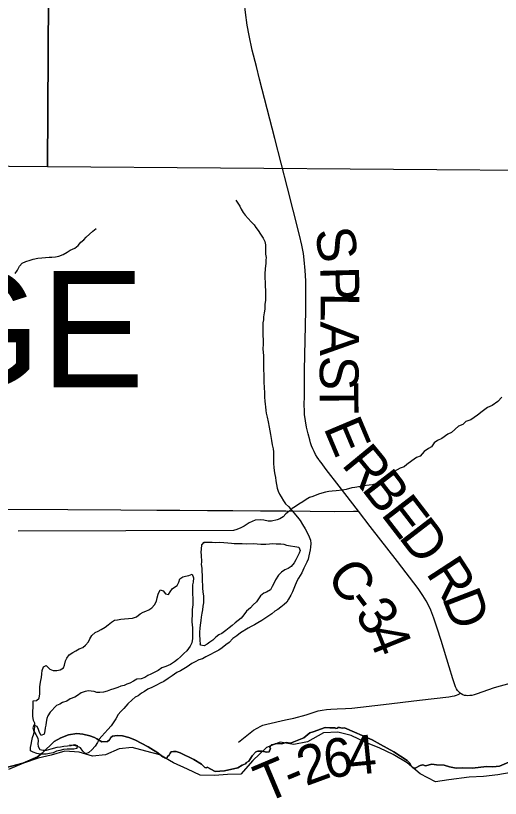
# Model space of a CAD drawing. Extents: x 0 to 34, y 0 to 22.
# Drawn here: x 4.767 to 5.123, y 17.478 to 18.052 of the extents above; entities that cross this region are included whole.
import ezdxf

# ---------------------------------------------------------------- set-up
doc = ezdxf.new("R2010")
doc.units = 0
for name, color, linetype in [('GM_X_Corporation', 7, 'Continuous'), ('GM_X_County_Road', 7, 'Continuous'), ('GM_X_County_Road_Text', 7, 'Continuous'), ('GM_X_Major_Lake', 7, 'Continuous'), ('GM_X_Minor_River', 7, 'Continuous'), ('GM_X_Township_Road', 7, 'Continuous'), ('GM_X_Township_Road_Text', 7, 'Continuous'), ('GM_X_Township_Text', 7, 'Continuous')]:
    doc.layers.add(name, color=color, linetype=linetype)

msp = doc.modelspace()

# ---------------------------------------------------------------- linework, layer by layer
at = {"layer": 'GM_X_Corporation'}
for points in [[(4.78631, 18.43953), (4.79371, 18.43949), (4.7909, 17.94084), (4.28639, 17.94519), (4.29299, 18.44647)], [(5.2907, 18.43288), (5.30482, 18.43261), (5.30041, 17.93698), (5.29864, 17.93686), (4.7909, 17.94084), (4.79371, 18.43949)]]:
    msp.add_lwpolyline(points, close=True, dxfattribs=at)
for points in [[(4.75985, 17.50015), (4.77274, 17.50363), (4.78345, 17.50836), (4.78698, 17.51101), (4.79573, 17.51947), (4.80055, 17.52212), (4.8063, 17.52438), (4.81225, 17.52546), (4.81677, 17.52502), (4.82183, 17.5236), (4.82532, 17.52247), (4.82704, 17.52153), (4.83073, 17.51927), (4.83496, 17.51957), (4.83628, 17.5207), (4.83727, 17.52247), (4.8385, 17.5234), (4.84022, 17.52375), (4.84228, 17.52394), (4.84597, 17.5236), (4.85044, 17.52242), (4.85486, 17.52075), (4.86465, 17.51563), (4.86863, 17.51328), (4.87113, 17.51165), (4.87546, 17.50821), (4.87728, 17.50738), (4.87861, 17.50758), (4.87885, 17.50856), (4.88008, 17.50944), (4.88082, 17.51092), (4.8817, 17.51205), (4.88337, 17.51229), (4.88519, 17.5122), (4.88824, 17.51111), (4.89817, 17.50644), (4.90382, 17.50286), (4.90632, 17.50054), (4.90752, 17.50019), (4.90795, 17.50064), (4.91399, 17.49765), (4.92063, 17.49804), (4.93056, 17.50015), (4.9338, 17.50207), (4.93616, 17.50305), (4.93695, 17.50418), (4.93851, 17.50511), (4.94108, 17.509), (4.94378, 17.512), (4.94506, 17.51249), (4.94811, 17.51244), (4.95179, 17.51175), (4.95346, 17.51195), (4.95435, 17.5147), (4.95386, 17.51519), (4.9544, 17.51642), (4.95528, 17.51711), (4.95617, 17.51721), (4.95794, 17.5178), (4.96015, 17.51804), (4.96275, 17.5179), (4.966, 17.51868), (4.96909, 17.51834), (4.97897, 17.52217), (4.98345, 17.52601), (4.9858, 17.52655), (4.9946, 17.52979), (4.99795, 17.52959), (5.00188, 17.52954), (5.00237, 17.52915), (5.00355, 17.5293), (5.0038, 17.52984), (5.00522, 17.52989), (5.00704, 17.5294), (5.00876, 17.52945), (5.02896, 17.5208), (5.03525, 17.51741), (5.04508, 17.51185), (5.05467, 17.50571), (5.05653, 17.50399), (5.05781, 17.50123), (5.05899, 17.50025), (5.06061, 17.5001), (5.0642, 17.50192), (5.06622, 17.50232), (5.06809, 17.50173), (5.07276, 17.503), (5.07615, 17.50232), (5.08195, 17.50212), (5.08578, 17.50099), (5.09074, 17.49991), (5.09571, 17.50025), (5.10244, 17.49991), (5.11311, 17.50109), (5.11753, 17.50084), (5.12255, 17.50153), (5.131, 17.50507)], [(5.131, 17.50507), (5.12255, 17.50153), (5.11753, 17.50084), (5.11311, 17.50109), (5.10244, 17.49991), (5.09571, 17.50025), (5.09074, 17.49991), (5.08578, 17.50099), (5.08195, 17.50212), (5.07615, 17.50232), (5.07276, 17.503), (5.06809, 17.50173), (5.06622, 17.50232), (5.0642, 17.50192), (5.06061, 17.5001), (5.05899, 17.50025), (5.05781, 17.50123), (5.05653, 17.50399), (5.05467, 17.50571), (5.04508, 17.51185), (5.03525, 17.51741), (5.02896, 17.5208), (5.00876, 17.52945), (5.00704, 17.5294), (5.00522, 17.52989), (5.0038, 17.52984), (5.00355, 17.5293), (5.00237, 17.52915), (5.00188, 17.52954), (4.99795, 17.52959), (4.9946, 17.52979), (4.9858, 17.52655), (4.98345, 17.52601), (4.97897, 17.52217), (4.96909, 17.51834), (4.966, 17.51868), (4.96275, 17.5179), (4.96015, 17.51804), (4.95794, 17.5178), (4.95617, 17.51721), (4.95528, 17.51711), (4.9544, 17.51642), (4.95386, 17.51519), (4.95435, 17.5147), (4.95346, 17.51195), (4.95179, 17.51175), (4.94811, 17.51244), (4.94506, 17.51249), (4.94378, 17.512), (4.94108, 17.509), (4.93851, 17.50511), (4.93695, 17.50418), (4.93616, 17.50305), (4.9338, 17.50207), (4.93056, 17.50015), (4.92063, 17.49804), (4.91399, 17.49765), (4.90795, 17.50064), (4.90752, 17.50019), (4.90632, 17.50054), (4.90382, 17.50286), (4.89817, 17.50644), (4.88824, 17.51111), (4.88519, 17.5122), (4.88337, 17.51229), (4.8817, 17.51205), (4.88082, 17.51092), (4.88008, 17.50944), (4.87885, 17.50856), (4.87861, 17.50758), (4.87728, 17.50738), (4.87546, 17.50821), (4.87113, 17.51165), (4.86863, 17.51328), (4.86465, 17.51563), (4.85486, 17.52075), (4.85044, 17.52242), (4.84597, 17.5236), (4.84228, 17.52394), (4.84022, 17.52375), (4.8385, 17.5234), (4.83727, 17.52247), (4.83628, 17.5207), (4.83496, 17.51957), (4.83073, 17.51927), (4.82704, 17.52153), (4.82532, 17.52247), (4.82183, 17.5236), (4.81677, 17.52502), (4.81225, 17.52546), (4.8063, 17.52438), (4.80055, 17.52212), (4.79573, 17.51947), (4.78698, 17.51101), (4.78345, 17.50836), (4.77274, 17.50363), (4.75985, 17.50015)]]:
    msp.add_lwpolyline(points, dxfattribs=at)
at = {"layer": 'GM_X_County_Road'}
for points in [[(4.94648, 18.00525), (4.94411, 18.01443), (4.94111, 18.02652), (4.93882, 18.03718), (4.93744, 18.04485), (4.93608, 18.0541), (4.93546, 18.06031), (4.93524, 18.06499), (4.93522, 18.07434), (4.93569, 18.08834), (4.93636, 18.1018)], [(4.9902, 17.72584), (4.98994, 17.7262), (4.98872, 17.72797), (4.98753, 17.72992), (4.98648, 17.73208), (4.98551, 17.73418), (4.98461, 17.73634), (4.98386, 17.73851), (4.98322, 17.74083), (4.98199, 17.74501), (4.98087, 17.74995), (4.98013, 17.75458), (4.97953, 17.75921), (4.97938, 17.76258), (4.97923, 17.76579), (4.9793, 17.77326), (4.97952, 17.79187), (4.98033, 17.83546), (4.98051, 17.851), (4.9804, 17.8572), (4.97996, 17.86495), (4.97927, 17.87267), (4.97864, 17.87727), (4.97749, 17.88335), (4.9757, 17.8909), (4.97109, 17.90899), (4.96694, 17.92557), (4.95771, 17.96173), (4.94648, 18.00525)], [(5.01914, 17.68832), (5.0049, 17.70683), (4.99524, 17.71903), (4.99154, 17.72405), (4.9902, 17.72584)], [(4.5969, 17.69027), (4.60848, 17.69021), (4.62713, 17.69011), (4.63955, 17.68998), (4.65974, 17.69015), (4.67061, 17.68997), (4.69856, 17.69002), (4.75604, 17.68978), (4.80574, 17.68966), (4.84457, 17.68932), (4.87097, 17.68923), (4.88806, 17.68922), (4.90825, 17.68887), (4.92689, 17.68884), (4.94708, 17.68868), (4.96572, 17.68856), (5.00144, 17.68822), (5.01541, 17.6883), (5.01914, 17.68832)], [(5.09373, 17.55489), (5.09309, 17.55543), (5.09243, 17.55608), (5.09171, 17.55697), (5.09092, 17.55821), (5.09021, 17.55955), (5.08963, 17.561), (5.08826, 17.56547), (5.08553, 17.57438), (5.07961, 17.59371), (5.07685, 17.60261), (5.07431, 17.60994), (5.07205, 17.61572), (5.07016, 17.61994), (5.0687, 17.62266), (5.06627, 17.6266), (5.0627, 17.63166), (5.04768, 17.65149), (5.02765, 17.67726), (5.01914, 17.68832)], [(5.13646, 17.56373), (5.12295, 17.56022), (5.11852, 17.55885), (5.10531, 17.55416), (5.10379, 17.55371), (5.10223, 17.55338), (5.10077, 17.55317), (5.09932, 17.55312), (5.09814, 17.55319), (5.09685, 17.55338), (5.09557, 17.55381), (5.09439, 17.55443), (5.09373, 17.55489)]]:
    msp.add_lwpolyline(points, dxfattribs=at)
at = {"layer": 'GM_X_Major_Lake'}
for points in [[(5.13104, 17.4968), (5.12137, 17.49509), (5.11074, 17.49395), (5.10012, 17.49337), (5.08532, 17.49147), (5.07564, 17.48995), (5.06426, 17.49584), (5.05477, 17.50382), (5.04452, 17.5099), (5.03465, 17.51465), (5.02441, 17.51884), (5.01359, 17.52397), (5.00392, 17.52644), (4.99348, 17.52586), (4.98153, 17.5194), (4.97147, 17.51731), (4.9616, 17.51902)], [(4.9616, 17.51902), (4.95155, 17.51502), (4.94149, 17.50571), (4.93277, 17.49563), (4.9229, 17.49544), (4.91341, 17.49449), (4.90298, 17.49487), (4.89349, 17.49924), (4.88325, 17.50399), (4.87319, 17.50969), (4.86294, 17.51235), (4.85308, 17.5152), (4.8434, 17.51425), (4.83334, 17.50987), (4.82386, 17.50873), (4.81399, 17.51177), (4.80355, 17.51253), (4.7935, 17.50949), (4.78401, 17.5074), (4.7732, 17.50359), (4.76219, 17.49903)]]:
    msp.add_lwpolyline(points, dxfattribs=at)
at = {"layer": 'GM_X_Minor_River'}
for points in [[(4.92908, 17.91636), (4.93061, 17.91428), (4.93195, 17.912), (4.93291, 17.90992), (4.93444, 17.90745), (4.93578, 17.90537), (4.93807, 17.90291), (4.94036, 17.90064), (4.94246, 17.89837), (4.9438, 17.89628), (4.94533, 17.8942), (4.94724, 17.89155), (4.94897, 17.88852), (4.95031, 17.88605), (4.95089, 17.88377), (4.9509, 17.88073), (4.95092, 17.87693), (4.95132, 17.87446), (4.95114, 17.87237), (4.95096, 17.87009), (4.9506, 17.86629), (4.95043, 17.8623), (4.95047, 17.85336), (4.95068, 17.85032), (4.95072, 17.8431), (4.95035, 17.84006), (4.95037, 17.83664), (4.94982, 17.83379), (4.94945, 17.83093), (4.94927, 17.82865), (4.9489, 17.82656), (4.94873, 17.82409), (4.94876, 17.81706), (4.94897, 17.81421), (4.94898, 17.81079), (4.94881, 17.80755), (4.94901, 17.80471), (4.94922, 17.80262), (4.94943, 17.79825), (4.94945, 17.79387), (4.94948, 17.78703), (4.9497, 17.78285), (4.94971, 17.77943), (4.95012, 17.77487), (4.95013, 17.77202), (4.95033, 17.76917), (4.95054, 17.76689), (4.95074, 17.7648), (4.95094, 17.76233), (4.95133, 17.76025), (4.95191, 17.7574), (4.95269, 17.75398), (4.95347, 17.74999), (4.95405, 17.74734), (4.95445, 17.74468), (4.95523, 17.74031), (4.95581, 17.73708), (4.9564, 17.73423), (4.9566, 17.73195), (4.95664, 17.72302), (4.95685, 17.72074), (4.95724, 17.71789), (4.95763, 17.71542), (4.95802, 17.71314), (4.95842, 17.71068), (4.95881, 17.70802), (4.95939, 17.70517), (4.96016, 17.70308), (4.96112, 17.701), (4.96227, 17.69891), (4.964, 17.69607), (4.96553, 17.69379), (4.96762, 17.69191), (4.97431, 17.68395), (4.97622, 17.68149), (4.97794, 17.67865), (4.97986, 17.67543), (4.98139, 17.67277), (4.98292, 17.66955), (4.9837, 17.66727), (4.98409, 17.6648), (4.98372, 17.66214), (4.98354, 17.66005), (4.98318, 17.65777), (4.98262, 17.65568), (4.98206, 17.6532), (4.98112, 17.65111), (4.9798, 17.64863), (4.97905, 17.64654), (4.97736, 17.64311), (4.97511, 17.6393), (4.97379, 17.6372), (4.9721, 17.63301), (4.9706, 17.62939), (4.96929, 17.62673), (4.96778, 17.62387), (4.96646, 17.62177), (4.96438, 17.62005), (4.96212, 17.61795), (4.95985, 17.61623), (4.95776, 17.61508)], [(4.76705, 17.86277), (4.76874, 17.86506), (4.77025, 17.86811), (4.77232, 17.87021), (4.77498, 17.87136), (4.7782, 17.87251), (4.78028, 17.87309), (4.7837, 17.87387), (4.78673, 17.87426), (4.79204, 17.87467), (4.79413, 17.87468), (4.7966, 17.87488), (4.79925, 17.87546), (4.80229, 17.87662), (4.80531, 17.87834), (4.80759, 17.87968), (4.81099, 17.88122), (4.81326, 17.88332), (4.81534, 17.88561), (4.81761, 17.88733), (4.8193, 17.88943), (4.82157, 17.89153), (4.82403, 17.89363), (4.82649, 17.89555)], [(5.12421, 17.77189), (5.12138, 17.76883), (5.11703, 17.76577), (5.1138, 17.76443), (5.10983, 17.76137), (5.10624, 17.75869), (5.10151, 17.75544), (5.09791, 17.75409), (5.09564, 17.75199), (5.09242, 17.75064), (5.08732, 17.74606), (5.08467, 17.7449), (5.08013, 17.74165), (5.07691, 17.74031), (5.07464, 17.7384), (5.07257, 17.73554), (5.0703, 17.73438), (5.06727, 17.73209), (5.06425, 17.72884), (5.0616, 17.72788), (5.05819, 17.7254), (5.0546, 17.72272), (5.05252, 17.72081), (5.04968, 17.71984), (5.04513, 17.71754), (5.04135, 17.71505), (5.03814, 17.71276), (5.03492, 17.71027), (5.03246, 17.70874), (5.02943, 17.70778), (5.02696, 17.70739), (5.02279, 17.70699), (5.02051, 17.70659), (5.01634, 17.70582), (5.01406, 17.70543), (5.01008, 17.70427), (5.00724, 17.70387), (5.00268, 17.70328), (4.99984, 17.70308), (4.99737, 17.70288), (4.99491, 17.70229), (4.99225, 17.70152), (4.98979, 17.70094), (4.98543, 17.69921), (4.98297, 17.69844), (4.9807, 17.69691), (4.97824, 17.69518), (4.97521, 17.69365), (4.97275, 17.69174), (4.97029, 17.6904), (4.96802, 17.68829), (4.96575, 17.68638), (4.96387, 17.68429), (4.96141, 17.68275), (4.95932, 17.68217), (4.95515, 17.6812), (4.95268, 17.68119), (4.94964, 17.68175), (4.94679, 17.68212), (4.94319, 17.68191), (4.93883, 17.6798)], [(4.93883, 17.6798), (4.93505, 17.6775), (4.93277, 17.67616), (4.92974, 17.675), (4.92728, 17.67423)], [(4.92728, 17.67423), (4.76934, 17.67387)], [(4.90322, 17.59012), (4.90282, 17.59468), (4.90261, 17.59715), (4.9026, 17.59981), (4.90297, 17.60266), (4.90314, 17.60494), (4.90351, 17.60817), (4.90388, 17.61065), (4.90443, 17.61369), (4.9048, 17.61597), (4.90516, 17.61882), (4.90553, 17.62111), (4.9055, 17.62624), (4.90511, 17.62909), (4.9049, 17.63213), (4.9047, 17.63441), (4.90469, 17.63688), (4.90449, 17.63935), (4.90448, 17.64144), (4.90427, 17.6441), (4.90426, 17.64657), (4.90387, 17.64923), (4.90405, 17.65132), (4.90383, 17.65607), (4.90363, 17.65835), (4.90381, 17.66063), (4.90417, 17.66367), (4.90587, 17.66577), (4.90872, 17.66559), (4.91176, 17.66561), (4.91442, 17.66543), (4.91726, 17.66563), (4.92011, 17.66546), (4.92315, 17.66509), (4.92581, 17.66491), (4.9279, 17.66473), (4.93378, 17.66476), (4.93663, 17.66458), (4.94195, 17.66461), (4.9446, 17.66443), (4.94745, 17.66425), (4.95106, 17.66427), (4.95372, 17.66447), (4.95618, 17.66467), (4.95865, 17.6645), (4.96207, 17.66451), (4.96416, 17.66414), (4.96625, 17.66358), (4.97537, 17.6621), (4.97614, 17.65964), (4.97558, 17.65754), (4.97427, 17.65507), (4.97314, 17.65278), (4.97182, 17.65049), (4.96975, 17.64782), (4.96748, 17.64629), (4.96501, 17.64533), (4.96255, 17.6438), (4.96029, 17.64151), (4.95822, 17.63808), (4.95709, 17.63598), (4.95577, 17.63312), (4.95446, 17.63084), (4.95162, 17.62911), (4.94953, 17.62834), (4.94708, 17.62624), (4.94425, 17.62205), (4.94179, 17.61976), (4.93972, 17.61747), (4.93688, 17.61498), (4.93481, 17.61231), (4.93292, 17.61002), (4.93065, 17.6083), (4.92857, 17.60658), (4.92631, 17.60448), (4.92404, 17.60295), (4.92158, 17.60104), (4.91874, 17.59874), (4.91666, 17.59778), (4.91439, 17.59606), (4.91212, 17.59377), (4.91004, 17.59243), (4.90796, 17.5909), (4.90569, 17.58956), (4.90322, 17.59012), (4.90276, 17.59112)], [(4.90547, 17.66437), (4.90532, 17.66508)], [(4.85328, 17.60996), (4.85395, 17.61022), (4.85604, 17.61099), (4.85887, 17.6131), (4.86095, 17.61425), (4.86304, 17.61502), (4.86512, 17.61598), (4.86739, 17.61751), (4.86947, 17.6198), (4.87078, 17.62246), (4.87134, 17.62494), (4.87209, 17.6276), (4.87359, 17.63084), (4.87568, 17.6299), (4.8774, 17.62782), (4.87968, 17.62726), (4.88081, 17.62935), (4.88251, 17.63164), (4.88591, 17.63394), (4.88723, 17.63641), (4.88797, 17.63889), (4.89006, 17.64023), (4.89214, 17.64081), (4.89461, 17.6412), (4.89688, 17.64216), (4.89803, 17.63951), (4.89767, 17.63646), (4.8973, 17.63437), (4.89732, 17.62962), (4.89734, 17.62734), (4.89754, 17.62487), (4.89755, 17.62221), (4.89737, 17.61974), (4.89701, 17.61632), (4.89704, 17.61157), (4.89686, 17.60947), (4.89687, 17.60719), (4.89707, 17.6051), (4.89727, 17.60282), (4.8973, 17.59769), (4.89712, 17.59503), (4.89676, 17.5918), (4.89563, 17.58932), (4.89299, 17.58589), (4.89091, 17.58417), (4.88846, 17.58169), (4.88619, 17.57959), (4.88392, 17.57786), (4.88108, 17.57595), (4.87767, 17.57441), (4.87483, 17.57345), (4.87199, 17.57154), (4.86953, 17.57039), (4.86669, 17.56885), (4.86442, 17.56789), (4.86215, 17.56655), (4.85949, 17.56559), (4.85646, 17.56519), (4.854, 17.56385), (4.85135, 17.56232), (4.84907, 17.56155), (4.84699, 17.56059), (4.84472, 17.56001), (4.84244, 17.55924), (4.8396, 17.55808), (4.83695, 17.55731), (4.83467, 17.55654), (4.83183, 17.55577), (4.82936, 17.55537), (4.82708, 17.55555), (4.82499, 17.55611), (4.8229, 17.55648), (4.82081, 17.55666), (4.81854, 17.55608), (4.81551, 17.55512), (4.81286, 17.55321), (4.81078, 17.55206), (4.80756, 17.55071), (4.8051, 17.54918), (4.80187, 17.54802), (4.79979, 17.54687), (4.79752, 17.54591), (4.7928, 17.54114), (4.7911, 17.53847), (4.79035, 17.53638), (4.7898, 17.53371), (4.78962, 17.53162), (4.78925, 17.52953), (4.78888, 17.52725), (4.78832, 17.52496), (4.78624, 17.524), (4.7849, 17.52609), (4.78432, 17.52837), (4.78317, 17.53064), (4.78089, 17.53158), (4.78014, 17.52949), (4.78091, 17.52702), (4.78225, 17.52456), (4.78378, 17.52209), (4.78398, 17.52), (4.7838, 17.51791)], [(4.87296, 17.62114), (4.87307, 17.62114)], [(4.95776, 17.61508), (4.9555, 17.61317), (4.9502, 17.60972), (4.94812, 17.60819), (4.94528, 17.60647), (4.94282, 17.60513), (4.94017, 17.60378), (4.93809, 17.60263), (4.93241, 17.59919), (4.92976, 17.59689), (4.92692, 17.59517), (4.92409, 17.59212), (4.92163, 17.59039), (4.91899, 17.58829), (4.91653, 17.58638), (4.90706, 17.58158), (4.9046, 17.58024), (4.90195, 17.57947), (4.8993, 17.57794), (4.89664, 17.57678), (4.89324, 17.5743), (4.88832, 17.57123), (4.88586, 17.57008), (4.88226, 17.56778), (4.87943, 17.56568), (4.87621, 17.56358), (4.87356, 17.56223), (4.87072, 17.56089), (4.86731, 17.55916), (4.86447, 17.55782), (4.86201, 17.5561), (4.85993, 17.55495), (4.85747, 17.55304), (4.8552, 17.55207), (4.85293, 17.55016), (4.84972, 17.54711), (4.84689, 17.54367), (4.84462, 17.54157), (4.84273, 17.53928), (4.84104, 17.53604), (4.83897, 17.53318), (4.83746, 17.5309), (4.8352, 17.52822), (4.83293, 17.52593), (4.83066, 17.52345), (4.82878, 17.52116), (4.82765, 17.51869), (4.82577, 17.51621), (4.82331, 17.51334), (4.82123, 17.51144), (4.81896, 17.51047), (4.81667, 17.51255), (4.81514, 17.51483), (4.81229, 17.51614), (4.80982, 17.51651), (4.80697, 17.51688)], [(4.7838, 17.51791), (4.784, 17.51582), (4.78534, 17.51374), (4.78763, 17.51318), (4.79009, 17.51319), (4.79351, 17.51416), (4.79805, 17.51532), (4.80033, 17.51571), (4.8028, 17.5161), (4.80564, 17.5163), (4.80811, 17.5167), (4.81057, 17.51728), (4.81267, 17.51653), (4.8123, 17.51443), (4.81021, 17.51385), (4.80736, 17.51384), (4.80528, 17.51383), (4.80262, 17.51363), (4.79978, 17.51304), (4.7975, 17.51246), (4.79504, 17.51131), (4.79238, 17.51073), (4.78992, 17.51034), (4.78536, 17.51032), (4.78308, 17.51069), (4.78042, 17.51162), (4.77833, 17.51275), (4.77831, 17.51523), (4.77887, 17.51732), (4.77924, 17.51998), (4.77979, 17.52245), (4.78073, 17.52512), (4.78128, 17.52816), (4.78165, 17.53044), (4.78145, 17.53291), (4.78068, 17.535), (4.78009, 17.53804), (4.78007, 17.54203), (4.78025, 17.54431), (4.78024, 17.54697), (4.78042, 17.54944), (4.78269, 17.54964), (4.78477, 17.55136), (4.78514, 17.55441), (4.78531, 17.55726), (4.7853, 17.55935), (4.78548, 17.56163), (4.78584, 17.56429), (4.7864, 17.56658), (4.78677, 17.56905), (4.78695, 17.57152), (4.78788, 17.57419), (4.78997, 17.57534), (4.79264, 17.57269), (4.79511, 17.57156), (4.79758, 17.57157), (4.80004, 17.57196), (4.8025, 17.57349), (4.80344, 17.57559), (4.804, 17.57863), (4.80493, 17.58073), (4.80682, 17.58302), (4.80947, 17.58474), (4.81155, 17.58608), (4.8142, 17.58742), (4.81666, 17.58857), (4.81875, 17.5901), (4.82082, 17.59258), (4.82195, 17.59487), (4.82327, 17.59716), (4.82591, 17.59945), (4.82799, 17.60041), (4.83027, 17.60156), (4.8331, 17.60347), (4.83537, 17.605), (4.83783, 17.60692), (4.8401, 17.60845), (4.84219, 17.60884), (4.84465, 17.60923), (4.84731, 17.60943), (4.85328, 17.60996)]]:
    msp.add_lwpolyline(points, dxfattribs=at)
at = {"layer": 'GM_X_Township_Road'}
msp.add_lwpolyline([(4.93096, 17.51904), (4.93219, 17.51999), (4.93823, 17.52491), (4.94196, 17.52773), (4.94457, 17.52942), (4.94732, 17.53086), (4.94876, 17.53145), (4.95175, 17.53231), (4.96544, 17.53532), (4.97151, 17.53672), (4.98053, 17.53916), (4.98946, 17.54192), (4.99249, 17.54261), (4.99556, 17.54308), (4.99867, 17.54332), (5.00334, 17.54345), (5.00956, 17.54369), (5.01422, 17.54406), (5.03742, 17.54673), (5.06371, 17.54977), (5.08537, 17.55228), (5.08785, 17.55268), (5.08958, 17.55305), (5.09089, 17.55347), (5.09216, 17.55391), (5.0931, 17.55439), (5.09373, 17.55489)], dxfattribs=at)

# ---------------------------------------------------------------- texts
at = {"layer": 'GM_X_County_Road_Text'}
for s, rotation, p in [('S', 280.22708, (4.98676, 17.89412)), ('P', 271.47314, (4.99091, 17.86769)), ('L', 269.28857, (4.9914, 17.84881)), ('A', 269.22769, (4.99114, 17.82757)), ('S', 269.24931, (4.9908, 17.80256)), ('T', 270.25588, (4.99055, 17.78285)), ('E', 292.85038, (4.99308, 17.74969)), ('R', 309.48403, (5.00597, 17.72243)), ('B', 307.61619, (5.02066, 17.70461)), ('E', 307.61867, (5.0349, 17.68613)), ('D', 307.59192, (5.04787, 17.6693)), ('R', 303.08711, (5.06808, 17.64301)), ('C', 306.86444, (4.99464, 17.64025)), ('D', 291.06001, (5.0801, 17.62486)), ('-', 306.81136, (5.00863, 17.62159)), ('3', 305.75305, (5.01554, 17.61236)), ('4', 291.99759, (5.02489, 17.59974))]:
    msp.add_text(s, height=0.02841, rotation=rotation, dxfattribs=at).set_placement(p)
at = {"layer": 'GM_X_Township_Road_Text'}
for s, rotation, p in [('6', 7.7886, (4.99528, 17.49227)), ('4', 5.7049, (5.01235, 17.49461)), ('2', 20.15405, (4.98042, 17.48663)), ('T', 22.87897, (4.9504, 17.47403)), ('-', 22.5334, (4.96994, 17.48228))]:
    msp.add_text(s, height=0.02841, rotation=rotation, dxfattribs=at).set_placement(p)
at = {"layer": 'GM_X_Township_Text'}
msp.add_text('PORTAGE', height=0.085227, rotation=0.00001, dxfattribs=at).set_placement((4.3047, 17.77928))

doc.saveas('drawing.dxf')
